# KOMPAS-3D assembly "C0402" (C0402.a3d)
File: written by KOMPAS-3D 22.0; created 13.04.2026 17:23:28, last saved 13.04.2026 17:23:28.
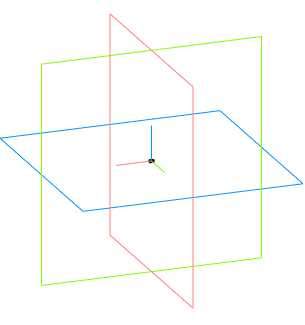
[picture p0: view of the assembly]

Document properties: Автор: Andrey; Полное имя файла: C:\Users\User1\Documents\C0402.a3d

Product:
- Component [detail]: C0402C103M4RAC  | qty 1  | source file: C0402C103M4RAC.m3d
- Part/product: C0402
    Комментарий: C0402

Referenced files in C:\Users\User1\Documents\: C0402C103M4RAC.m3d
